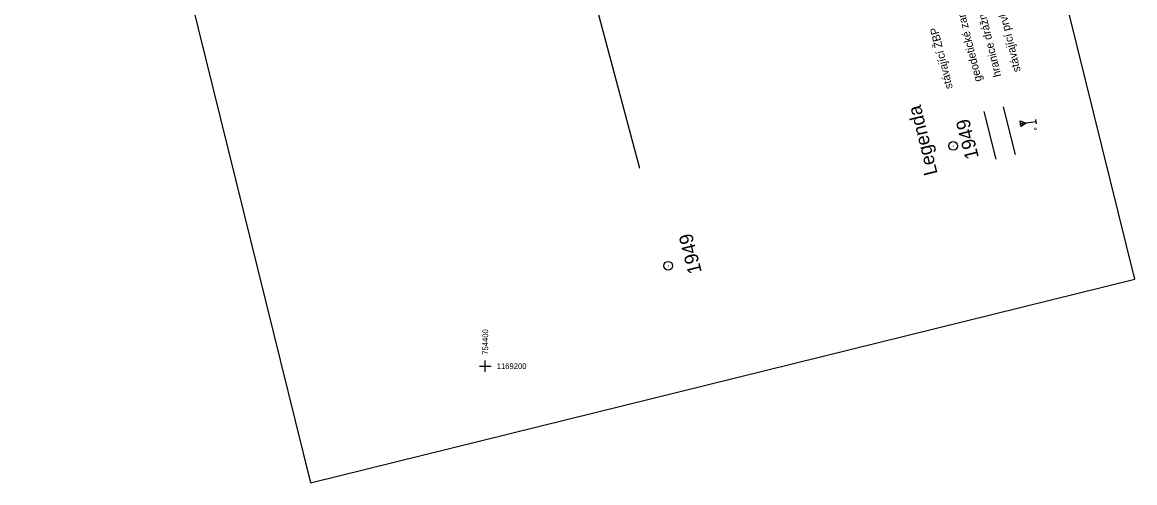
# Model space of a CAD drawing. Extents: x -754679 to -754173, y -1169241 to -1168288.
# Drawn here: x -754562 to -754172.8, y -1169240.8 to -1169079.6 of the extents above; entities that cross this region are included whole.
import ezdxf

# ---------------------------------------------------------------- set-up
doc = ezdxf.new("R2010")
doc.units = 0
for name, color, linetype in [('Default', 7, 'Continuous'), ('Vrstva 1', 7, 'Continuous'), ('Vrstva 2', 7, 'Continuous'), ('Vrstva 24', 7, 'Continuous'), ('Vrstva 27', 7, 'Continuous'), ('Vrstva 4', 7, 'Continuous'), ('Vrstva 53', 7, 'Continuous'), ('Vrstva 61', 7, 'Continuous'), ('Vrstva 63', 7, 'Continuous')]:
    doc.layers.add(name, color=color, linetype=linetype)

msp = doc.modelspace()

# ---------------------------------------------------------------- linework, layer by layer
at = {"layer": 'Default'}
for points in [[(-754400, -1169202), (-754400, -1169200), (-754400, -1169198)], [(-754402, -1169200), (-754400, -1169200), (-754398, -1169200)]]:
    msp.add_lwpolyline(points, dxfattribs=at)
at = {"layer": 'Vrstva 1'}
msp.add_line((-754335.99, -1169164.84), (-754335.99, -1169164.84), dxfattribs=at)
at = {"layer": 'Vrstva 24'}
msp.add_line((-754214.56, -1169125.87), (-754218.69, -1169109.2), dxfattribs=at)
at = {"layer": 'Vrstva 27'}
msp.add_line((-754221.36, -1169127.56), (-754225.49, -1169110.88), dxfattribs=at)
at = {"layer": 'Vrstva 4'}
for p, q in [((-754211.94, -1169115.26), (-754212.32, -1169114.96)), ((-754207.23, -1169115.24), (-754207.43, -1169113.7))]:
    msp.add_line(p, q, dxfattribs=at)
msp.add_lwpolyline([(-754207.33, -1169114.47), (-754210.78, -1169114.91), (-754212.64, -1169116.14), (-754212.9, -1169114.16), (-754210.78, -1169114.91)], dxfattribs=at)
msp.add_circle((-754212.13, -1169115.11), 0.248, dxfattribs=at)
at = {"layer": 'Vrstva 53'}
msp.add_lwpolyline([(-754345.91, -1169130.8), (-754386.06, -1168980.52), (-754394.57, -1168948.26)], dxfattribs=at)
at = {"layer": 'Vrstva 61'}
msp.add_line((-754561.97, -1168833.08), (-754461.15, -1169240.8), dxfattribs=at)
msp.add_lwpolyline([(-754461.15, -1169240.8), (-754172.83, -1169169.5), (-754273.65, -1168761.78), (-754561.97, -1168833.08)], dxfattribs=at)
at = {"layer": 'Vrstva 63'}
for p, q in [((-754236.38, -1169122.84), (-754236.37, -1169123.04)), ((-754336.09, -1169164.84), (-754335.89, -1169164.84))]:
    msp.add_line(p, q, dxfattribs=at)
for centre in [(-754236.38, -1169122.94), (-754335.99, -1169164.84)]:
    msp.add_circle(centre, 1.51, dxfattribs=at)

# ---------------------------------------------------------------- texts
at = {"layer": 'Default'}
msp.add_text('754400', height=2, rotation=90, dxfattribs=at).set_placement((-754399, -1169196))
msp.add_text('1169200', height=2, dxfattribs=at).set_placement((-754396, -1169201))
at = {"layer": 'Vrstva 2'}
for p in [(-754227.31, -1169126.93), (-754324.23, -1169167.04)]:
    msp.add_text('1949', height=4.8, rotation=104.3427, dxfattribs=at).set_placement(p)
at = {"layer": 'Vrstva 27'}
for s, height, p in [('stávající prvky zabezpečovacího zařízení', 2.8, (-754212.69, -1169096.75)), ('geodetické zaměření skutečného stavu', 2.8, (-754226.28, -1169100.11)), ('hranice drážního pozemku', 2.8, (-754219.49, -1169098.43)), ('stávající ŽBP', 2.8, (-754236.47, -1169102.63)), ('Legenda', 4.8, (-754241.74, -1169132.6))]:
    msp.add_text(s, height=height, rotation=103.9106, dxfattribs=at).set_placement(p)
at = {"layer": 'Vrstva 4'}
msp.add_text('B', height=1, rotation=100, dxfattribs=at).set_placement((-754207.04, -1169117.34))

doc.saveas('drawing.dxf')
